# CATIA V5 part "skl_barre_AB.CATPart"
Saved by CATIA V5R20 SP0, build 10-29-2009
Part number: skl_barre_AB
Publications: "Droite_AB", "Axe_pivot_AB_A", "Axe_pivot_AB_B"
Bounding box of the stored display mesh (mm): x 5 to 10, y -85.995 to -49.005, z 44.008 to 205.992
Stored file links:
  D:\Dropbox\IAO_2012\IAO_2012_742_prousseau\skl_barre_AB.CATPart
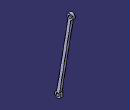
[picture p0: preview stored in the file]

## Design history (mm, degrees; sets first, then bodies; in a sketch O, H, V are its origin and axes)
Set1
  Line1 "Droite_AB": type PtPt, FirstPoint Point1, SecondPoint Point2
  Point1 "Point_A": stored without definition
  Point2 "Point_B": stored without definition
  Line2 "Axe_pivot_AB_A": type Normal, RefPoint Point1, RefSkin Plane1, Start -20, End 20
  Plane1 "Plan_Ref": stored without definition
  Line3 "Axe_pivot_AB_B": type Normal, RefPoint Point2, RefSkin Plane1, Start -20, End 20
  Plane2: type Offset, RefPlane Plane1, Offset 5
Body1 (main body)
  Sketch1 on Plane2, origin (5, 0, 0), H (0, 1, 0), V (0, 0, 1)
    point P1 (-52.8951, 194.3813)
    circle A1 centre (-80, 50) radius 3
    point P2 (-80, 50)
    reference projected point E1 (-80, 50) from Point1
    arc A2 centre (-80, 50) radius 6 from (-82.1049, 55.6187) to (-76.1866, 54.6323) ccw
    point P3 (-80, 50)
    reference projected point E2 (-80, 50) from Point1
    line L1 (-76.1866, 54.6323) -> (-52.8951, 194.3813)
    circle A3 centre (-55, 200) radius 3
    point P6 (-55, 200)
    reference projected point E3 (-55, 200) from Point2
    arc A4 centre (-55, 200) radius 6 from (-52.8951, 194.3813) to (-58.8134, 195.3677) ccw
    point P7 (-55, 200)
    reference projected point E4 (-55, 200) from Point2
    point P9 (-52.8951, 194.3813)
    line L2 (-58.8134, 195.3677) -> (-82.1049, 55.6187)
    reference projected line E5 (-80, 50) -> (-55, 200) from Line1
    reference projected line E6 (-80, 50) -> (-55, 200) from Line1
    reference projected line E7 (-80, 50) -> (-55, 200) from Line1
    radius A1 = 3
    radius A2 = 6
    radius A4 = 6
    radius A3 = 3
    distance L2 E7 = 3
    coincidence: P2 E1, P3 E2, P6 E3, P7 E4, P1 P9
    symmetry: L1 L2 E5
    parallelism: L1 E6
  Pad1: profile Sketch1, direction (1, 0, 0), length 5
